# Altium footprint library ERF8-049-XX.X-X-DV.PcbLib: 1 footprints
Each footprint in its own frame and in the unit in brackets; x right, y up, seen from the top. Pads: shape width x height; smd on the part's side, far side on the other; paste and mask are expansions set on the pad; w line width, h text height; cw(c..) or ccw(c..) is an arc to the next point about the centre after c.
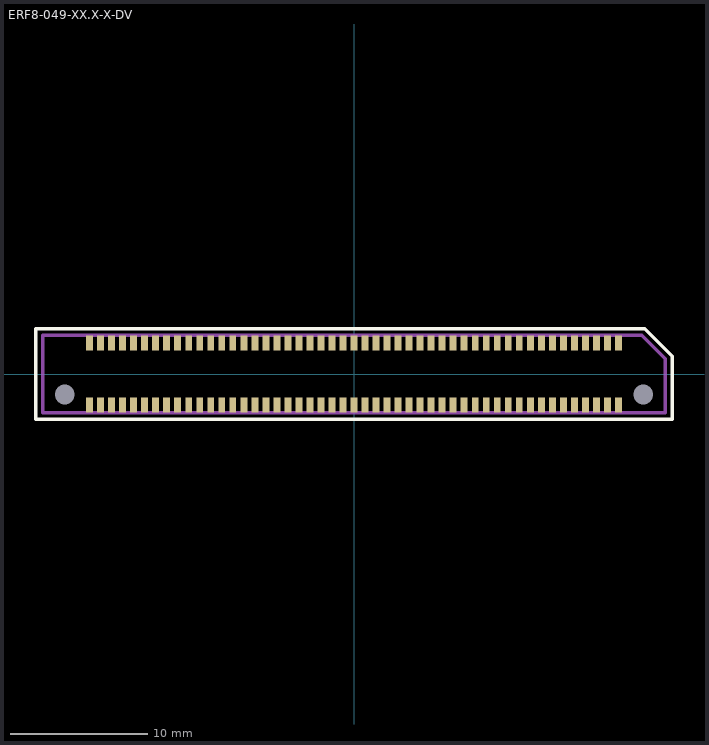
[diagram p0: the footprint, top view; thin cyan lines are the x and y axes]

## ERF8-049-XX.X-X-DV [mm]
pads (100):
  rect 0.5x1.1 smd mask+0.05: 1(19.2,2.25) 2(19.2,-2.25) 3(18.4,2.25) 4(18.4,-2.25) 5(17.6,2.25) 6(17.6,-2.25) 7(16.8,2.25) 8(16.8,-2.25) 9(16,2.25) 10(16,-2.25) 11(15.2,2.25) 12(15.2,-2.25) 13(14.4,2.25) 14(14.4,-2.25) 15(13.6,2.25) 16(13.6,-2.25) 17(12.8,2.25) 18(12.8,-2.25) 19(12,2.25) 20(12,-2.25) 21(11.2,2.25) 22(11.2,-2.25) 23(10.4,2.25) 24(10.4,-2.25) 25(9.6,2.25) 26(9.6,-2.25) 27(8.8,2.25) 28(8.8,-2.25) 29(8,2.25) 30(8,-2.25) 31(7.2,2.25) 32(7.2,-2.25) 33(6.4,2.25) 34(6.4,-2.25) 35(5.6,2.25) 36(5.6,-2.25) 37(4.8,2.25) 38(4.8,-2.25) 39(4,2.25) 40(4,-2.25) 41(3.2,2.25) 42(3.2,-2.25) 43(2.4,2.25) 44(2.4,-2.25) 45(1.6,2.25) 46(1.6,-2.25) 47(0.8,2.25) 48(0.8,-2.25) 49(0,2.25) 50(0,-2.25) 51(-0.8,2.25) 52(-0.8,-2.25) 53(-1.6,2.25) 54(-1.6,-2.25) 55(-2.4,2.25) 56(-2.4,-2.25) 57(-3.2,2.25) 58(-3.2,-2.25) 59(-4,2.25) 60(-4,-2.25) 61(-4.8,2.25) 62(-4.8,-2.25) 63(-5.6,2.25) 64(-5.6,-2.25) 65(-6.4,2.25) 66(-6.4,-2.25) 67(-7.2,2.25) 68(-7.2,-2.25) 69(-8,2.25) 70(-8,-2.25) 71(-8.8,2.25) 72(-8.8,-2.25) 73(-9.6,2.25) 74(-9.6,-2.25) 75(-10.4,2.25) 76(-10.4,-2.25) 77(-11.2,2.25) 78(-11.2,-2.25) 79(-12,2.25) 80(-12,-2.25) 81(-12.8,2.25) 82(-12.8,-2.25) 83(-13.6,2.25) 84(-13.6,-2.25) 85(-14.4,2.25) 86(-14.4,-2.25) 87(-15.2,2.25) 88(-15.2,-2.25) 89(-16,2.25) 90(-16,-2.25) 91(-16.8,2.25) 92(-16.8,-2.25) 93(-17.6,2.25) 94(-17.6,-2.25) 95(-18.4,2.25) 96(-18.4,-2.25) 97(-19.2,2.25) 98(-19.2,-2.25)
  round 0 hole 1.45 unplated: 99(21,-1.5) 100(-21,-1.5)
Top Overlay:
  lines w0.25: -23.1,-3.3 -23.1,3.3 21.1,3.3 23.1,1.3 23.1,-3.3 -23.1,-3.3
Mechanical 1:
  lines w0.25: -22.6,-2.8 -22.6,2.8 20.9,2.8 22.6,1.1 22.6,-2.8 -22.6,-2.8
  text "J1" at -0.839,-0.45 h0.75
